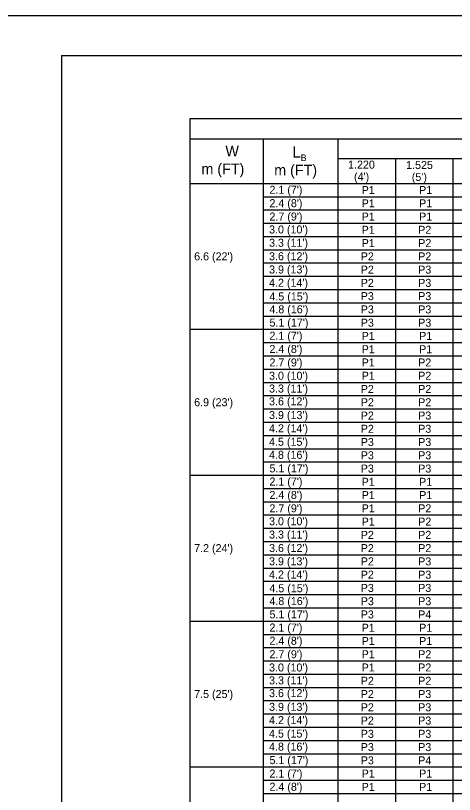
# Model space of a CAD drawing. Extents: x 637580 to 641008, y 294594 to 295782.
# Drawn here: x 640126.1 to 640290.4, y 295489.6 to 295781.6 of the extents above; entities that cross this region are included whole.
import ezdxf

# ---------------------------------------------------------------- set-up
doc = ezdxf.new("R2010")
doc.units = 0
for name, color, linetype in [('1', 7, 'Continuous'), ('2', 7, 'Continuous'), ('PLT-BNDY', 7, 'Continuous')]:
    doc.layers.add(name, color=color, linetype=linetype)

msp = doc.modelspace()

# ---------------------------------------------------------------- linework, layer by layer
at = {"layer": '1'}
for p, q in [((640143.31, 295766.63), (640929.31, 295766.63)), ((640143.31, 295766.63), (640143.31, 295202.63)), ((640191.43, 295226.43), (640191.43, 295743.08)), ((640191.43, 295743.08), (640526.66, 295743.08)), ((640191.43, 295735.41), (640526.66, 295735.41)), ((640218.95, 295226.43), (640218.95, 295735.41)), ((640191.43, 295718.7), (640526.66, 295718.7)), ((640191.43, 295664.01), (640526.66, 295664.01)), ((640191.43, 295609.31), (640526.66, 295609.31)), ((640191.43, 295554.61), (640526.66, 295554.61)), ((640191.43, 295499.91), (640526.66, 295499.91))]:
    msp.add_line(p, q, dxfattribs=at)
at = {"layer": '2'}
for p, q in [((640246.95, 295226.43), (640246.95, 295735.41)), ((640246.95, 295728.06), (640526.66, 295728.06)), ((640268.47, 295226.43), (640268.47, 295728.06)), ((640289.99, 295226.43), (640289.99, 295728.06)), ((640211.96, 295718.7), (640526.66, 295718.7)), ((640218.95, 295713.73), (640526.66, 295713.73)), ((640218.95, 295708.76), (640526.66, 295708.76)), ((640218.95, 295703.79), (640526.66, 295703.79)), ((640218.95, 295698.81), (640526.66, 295698.81)), ((640218.95, 295693.84), (640526.66, 295693.84)), ((640218.95, 295688.87), (640526.66, 295688.87)), ((640218.95, 295683.9), (640526.66, 295683.9)), ((640218.95, 295678.92), (640526.66, 295678.92)), ((640218.95, 295673.95), (640526.66, 295673.95)), ((640218.95, 295668.98), (640526.66, 295668.98)), ((640218.95, 295659.03), (640526.66, 295659.03)), ((640218.95, 295654.06), (640526.66, 295654.06)), ((640218.95, 295649.09), (640526.66, 295649.09)), ((640218.95, 295644.12), (640526.66, 295644.12)), ((640218.95, 295639.14), (640526.66, 295639.14)), ((640218.95, 295634.17), (640526.66, 295634.17)), ((640218.95, 295629.2), (640526.66, 295629.2)), ((640218.95, 295624.23), (640526.66, 295624.23)), ((640218.95, 295619.25), (640526.66, 295619.25)), ((640218.95, 295614.28), (640526.66, 295614.28)), ((640218.95, 295604.34), (640526.66, 295604.34)), ((640218.95, 295599.36), (640526.66, 295599.36)), ((640218.95, 295594.39), (640526.66, 295594.39)), ((640218.95, 295589.42), (640526.66, 295589.42)), ((640218.95, 295584.45), (640526.66, 295584.45)), ((640218.95, 295579.47), (640526.66, 295579.47)), ((640218.95, 295574.5), (640526.66, 295574.5)), ((640218.95, 295569.53), (640526.66, 295569.53)), ((640218.95, 295564.56), (640526.66, 295564.56)), ((640218.95, 295559.58), (640526.66, 295559.58)), ((640218.95, 295549.64), (640526.66, 295549.64)), ((640218.95, 295544.67), (640526.66, 295544.67)), ((640218.95, 295539.69), (640526.66, 295539.69)), ((640218.95, 295534.72), (640526.66, 295534.72)), ((640218.95, 295529.75), (640526.66, 295529.75)), ((640218.95, 295524.78), (640526.66, 295524.78)), ((640218.95, 295519.8), (640526.66, 295519.8)), ((640218.95, 295514.83), (640526.66, 295514.83)), ((640218.95, 295509.86), (640526.66, 295509.86)), ((640218.95, 295504.89), (640526.66, 295504.89)), ((640218.95, 295494.94), (640526.66, 295494.94)), ((640218.95, 295489.97), (640526.66, 295489.97))]:
    msp.add_line(p, q, dxfattribs=at)
at = {"layer": 'PLT-BNDY'}
msp.add_lwpolyline([(640103.31, 295781.63), (640944.31, 295781.63), (640944.31, 295187.63), (640103.31, 295187.63)], close=True, dxfattribs=at)

# ---------------------------------------------------------------- texts
at = {"layer": '1'}
for s, height, p in [('W', 4, (640204.67, 295728.83)), ('L', 4.3, (640229.7, 295728.36)), ('B', 2.5, (640232.83, 295727.05)), ('1.220', 3, (640250.61, 295724.23)), ('1.525', 3, (640272.36, 295724.12)), ('m (FT)', 4.003, (640195.69, 295722.13)), ('m (FT)', 4.003, (640222.95, 295721.72)), ("(4')", 3, (640252.85, 295719.73)), ("(5')", 3, (640274.48, 295719.62)), ("2.1 (7')", 3, (640221.16, 295714.83)), ('P1', 3, (640255.7, 295714.72)), ('P1', 3, (640277.22, 295714.72)), ("2.4 (8')", 3, (640221.16, 295709.79)), ('P1', 3, (640255.7, 295709.74)), ('P1', 3, (640277.22, 295709.74)), ("2.7 (9')", 3, (640221.16, 295704.78)), ('P1', 3, (640255.7, 295704.77)), ('P1', 3, (640277.22, 295704.77)), ("3.0 (10')", 3, (640221.01, 295699.93)), ('P1', 3, (640255.7, 295699.8)), ('P2', 3, (640276.88, 295699.8)), ("3.3 (11')", 3, (640221.01, 295694.95)), ('P1', 3, (640255.7, 295694.83)), ('P2', 3, (640276.88, 295694.83)), ("6.6 (22')", 3, (640192.95, 295689.85)), ("3.6 (12')", 3, (640221.01, 295689.9)), ('P2', 3, (640255.36, 295689.85)), ('P2', 3, (640276.88, 295689.85)), ("3.9 (13')", 3, (640221.01, 295684.93)), ('P2', 3, (640255.36, 295684.88)), ('P3', 3, (640276.88, 295684.88)), ("4.2 (14')", 3, (640221.01, 295679.95)), ('P2', 3, (640255.36, 295679.91)), ('P3', 3, (640276.88, 295679.91)), ("4.5 (15')", 3, (640221.14, 295674.82)), ('P3', 3, (640255.36, 295674.94)), ('P3', 3, (640276.88, 295674.94)), ("4.8 (16')", 3, (640221.14, 295670.01)), ('P3', 3, (640255.36, 295669.96)), ('P3', 3, (640276.88, 295669.96)), ("5.1 (17')", 3, (640221.17, 295665.03)), ('P3', 3, (640255.36, 295664.99)), ('P3', 3, (640276.88, 295664.99)), ("2.1 (7')", 3, (640221.16, 295660.1)), ('P1', 3, (640255.7, 295660.02)), ('P1', 3, (640277.22, 295660.02)), ("2.4 (8')", 3, (640221.16, 295655.13)), ('P1', 3, (640255.7, 295655.05)), ('P1', 3, (640277.22, 295655.05)), ("2.7 (9')", 3, (640221.16, 295650.08)), ('P1', 3, (640255.7, 295650.07)), ('P2', 3, (640276.88, 295650.07)), ("3.0 (10')", 3, (640221.01, 295645.1)), ('P1', 3, (640255.7, 295645.1)), ('P2', 3, (640276.88, 295645.1)), ("3.3 (11')", 3, (640221.01, 295640.3)), ('P2', 3, (640255.36, 295640.13)), ('P2', 3, (640276.88, 295640.13)), ("6.9 (23')", 3, (640192.95, 295635.16)), ("3.6 (12')", 3, (640221.01, 295635.5)), ('P2', 3, (640255.36, 295635.16)), ('P2', 3, (640276.88, 295635.16)), ("3.9 (13')", 3, (640221.01, 295630.35)), ('P2', 3, (640255.36, 295630.18)), ('P3', 3, (640276.88, 295630.18)), ("4.2 (14')", 3, (640221.01, 295625.38)), ('P2', 3, (640255.36, 295625.21)), ('P3', 3, (640276.88, 295625.21)), ("4.5 (15')", 3, (640221.01, 295620.33)), ('P3', 3, (640255.36, 295620.24)), ('P3', 3, (640276.88, 295620.24)), ("4.8 (16')", 3, (640221.01, 295615.44)), ('P3', 3, (640255.36, 295615.27)), ('P3', 3, (640276.88, 295615.27)), ("5.1 (17')", 3, (640221.17, 295610.37)), ('P3', 3, (640255.36, 295610.29)), ('P3', 3, (640276.88, 295610.29)), ("2.1 (7')", 3, (640221.16, 295605.44)), ('P1', 3, (640255.7, 295605.32)), ('P1', 3, (640277.22, 295605.32)), ("2.4 (8')", 3, (640221.16, 295600.39)), ('P1', 3, (640255.7, 295600.35)), ('P1', 3, (640277.22, 295600.35)), ("2.7 (9')", 3, (640221.16, 295595.38)), ('P1', 3, (640255.7, 295595.38)), ('P2', 3, (640276.88, 295595.38)), ("3.0 (10')", 3, (640221.01, 295590.53)), ('P1', 3, (640255.7, 295590.4)), ('P2', 3, (640276.88, 295590.4)), ("3.3 (11')", 3, (640221.01, 295585.56)), ('P2', 3, (640255.36, 295585.43)), ('P2', 3, (640276.88, 295585.43)), ("7.2 (24')", 3, (640192.95, 295580.46)), ("3.6 (12')", 3, (640221.01, 295580.5)), ('P2', 3, (640255.36, 295580.46)), ('P2', 3, (640276.88, 295580.46)), ("3.9 (13')", 3, (640221.01, 295575.53)), ('P2', 3, (640255.36, 295575.49)), ('P3', 3, (640276.88, 295575.49)), ("4.2 (14')", 3, (640221.01, 295570.56)), ('P2', 3, (640255.36, 295570.51)), ('P3', 3, (640276.88, 295570.51)), ("4.5 (15')", 3, (640221.14, 295565.42)), ('P3', 3, (640255.36, 295565.54)), ('P3', 3, (640276.88, 295565.54)), ("4.8 (16')", 3, (640221.14, 295560.61)), ('P3', 3, (640255.36, 295560.57)), ('P3', 3, (640276.88, 295560.57)), ("5.1 (17')", 3, (640221.17, 295555.63)), ('P3', 3, (640255.36, 295555.6)), ('P4', 3, (640276.88, 295555.6)), ("2.1 (7')", 3, (640221.16, 295550.7)), ('P1', 3, (640255.7, 295550.62)), ('P1', 3, (640277.22, 295550.62)), ("2.4 (8')", 3, (640221.16, 295545.74)), ('P1', 3, (640255.7, 295545.65)), ('P1', 3, (640277.22, 295545.65)), ("2.7 (9')", 3, (640221.16, 295540.68)), ('P1', 3, (640255.7, 295540.68)), ('P2', 3, (640276.88, 295540.68)), ("3.0 (10')", 3, (640221.01, 295535.71)), ('P1', 3, (640255.7, 295535.71)), ('P2', 3, (640276.88, 295535.71)), ("3.3 (11')", 3, (640221.01, 295530.9)), ('P2', 3, (640255.36, 295530.73)), ('P2', 3, (640276.88, 295530.73)), ("7.5 (25')", 3, (640192.95, 295525.76)), ("3.6 (12')", 3, (640221.01, 295526.1)), ('P2', 3, (640255.36, 295525.76)), ('P3', 3, (640276.88, 295525.76)), ("3.9 (13')", 3, (640221.01, 295520.96)), ('P2', 3, (640255.36, 295520.79)), ('P3', 3, (640276.88, 295520.79)), ("4.2 (14')", 3, (640221.01, 295515.99)), ('P2', 3, (640255.36, 295515.82)), ('P3', 3, (640276.88, 295515.82)), ("4.5 (15')", 3, (640221.01, 295510.93)), ('P3', 3, (640255.36, 295510.84)), ('P3', 3, (640276.88, 295510.84)), ("4.8 (16')", 3, (640221.01, 295506.04)), ('P3', 3, (640255.36, 295505.87)), ('P3', 3, (640276.88, 295505.87)), ("5.1 (17')", 3, (640221.17, 295500.98)), ('P3', 3, (640255.36, 295500.9)), ('P4', 3, (640276.88, 295500.9)), ("2.1 (7')", 3, (640221.16, 295495.96)), ('P1', 3, (640255.7, 295495.93)), ('P1', 3, (640277.22, 295495.93)), ("2.4 (8')", 3, (640221.16, 295491)), ('P1', 3, (640255.7, 295490.95)), ('P1', 3, (640277.22, 295490.95))]:
    msp.add_text(s, height=height, dxfattribs=at).set_placement(p)

doc.saveas('drawing.dxf')
